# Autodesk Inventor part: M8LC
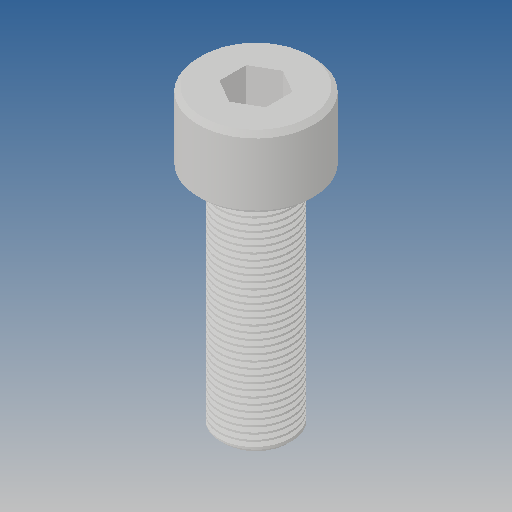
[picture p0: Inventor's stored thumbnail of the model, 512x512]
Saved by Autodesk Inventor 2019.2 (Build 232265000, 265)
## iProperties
Created: 2010-02
Part Number: M8LC
Material: Ogólny
Document SubType Name: Modeling
Designer: CADENGINEERING4
Density: 1 g/cm^3
Appearance: Domyślna
Author: CADENGINEERING4
Revision Number: 3LAST_VERSION
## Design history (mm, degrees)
feature "Baza1"
node "Bryła1"
